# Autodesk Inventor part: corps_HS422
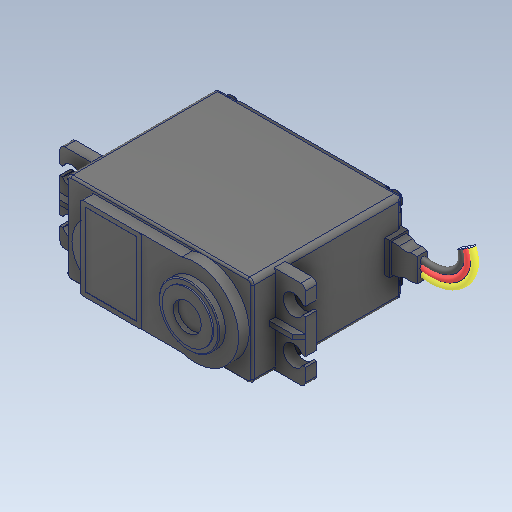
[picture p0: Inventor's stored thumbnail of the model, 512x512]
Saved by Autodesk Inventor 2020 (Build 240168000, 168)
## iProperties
Created: 2012-04
Part Number: corps_HS422
Material: Générique
Document SubType Name: Modeling
Designer: bruno
Density: 1 g/cm^3
Appearance: Par défaut
Author: bruno
Sending System: SolidWorks 2016
Last Author: Prof
Last Saved: 2018-11-12
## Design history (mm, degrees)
feature "Symétrie4"
node "Solide1"
